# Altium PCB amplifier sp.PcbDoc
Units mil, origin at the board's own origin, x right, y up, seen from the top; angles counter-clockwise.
Board outline 708.66 x 1338.58 mil, 2 copper layers (Top Layer, Bottom Layer); 37 components, 29 nets, 115 pads, 41 vias.
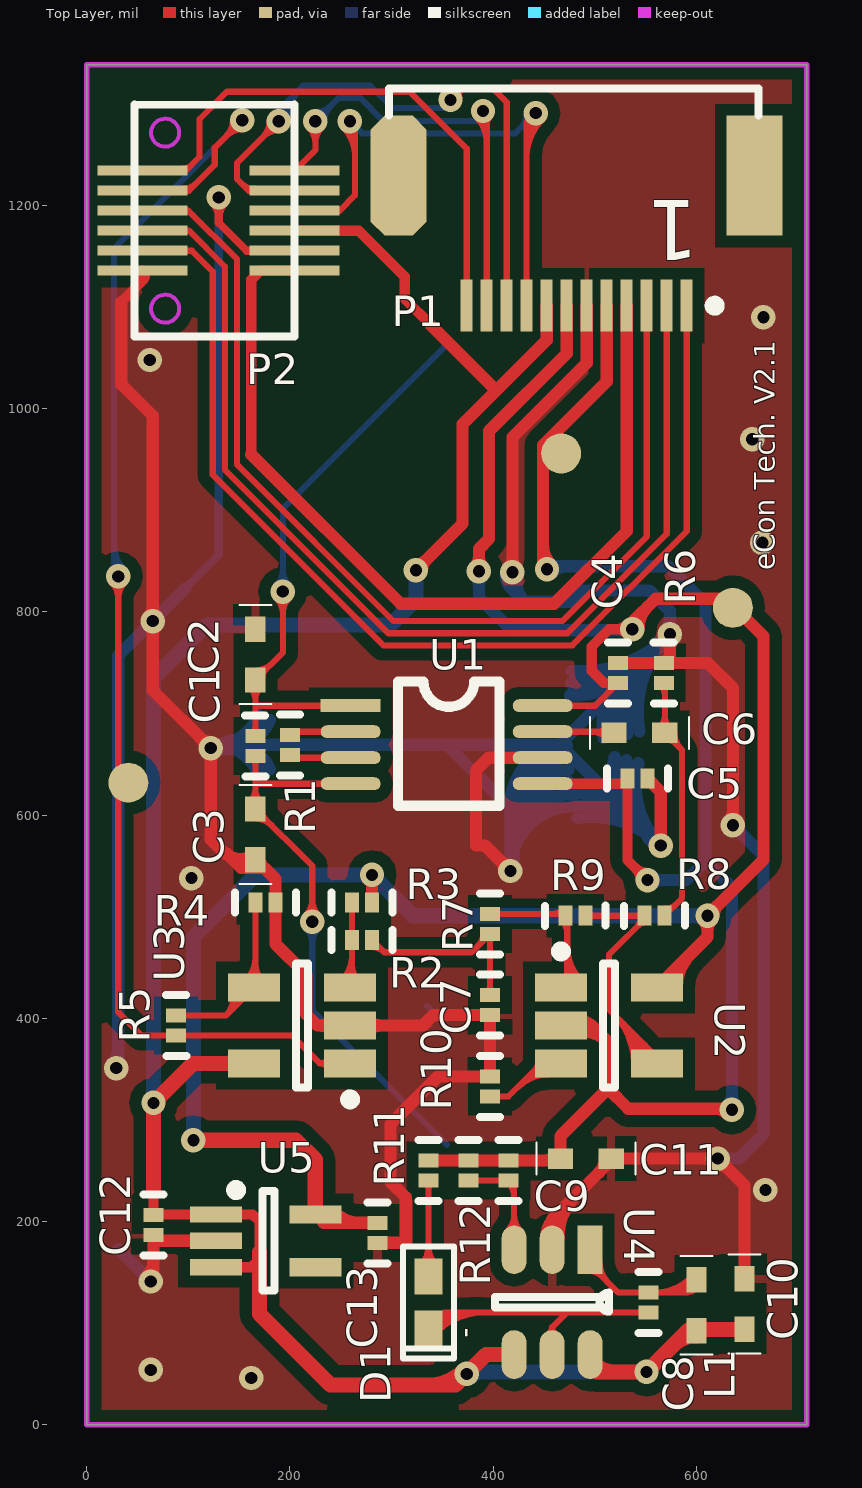
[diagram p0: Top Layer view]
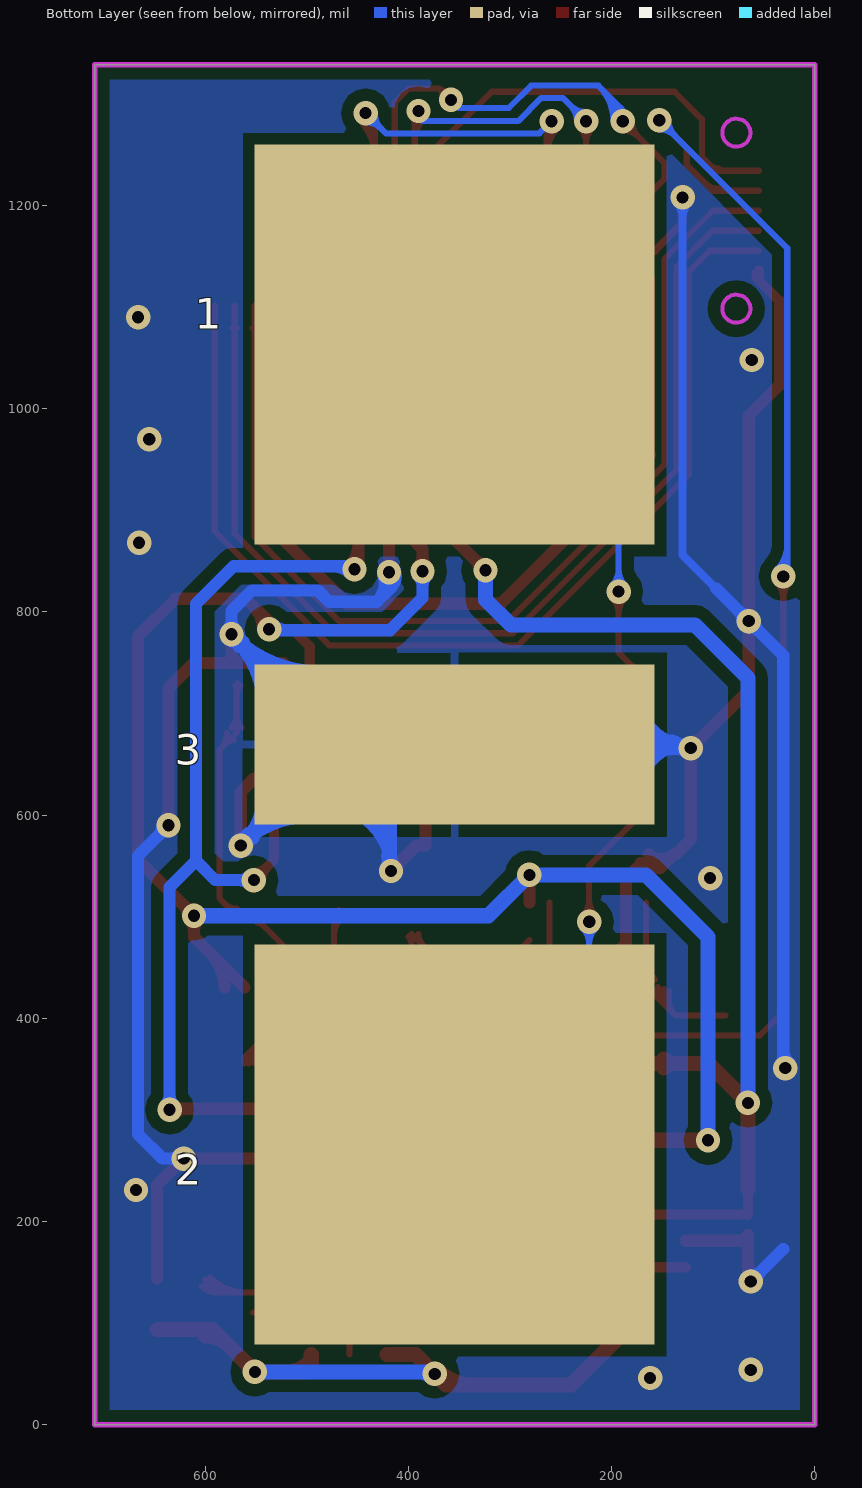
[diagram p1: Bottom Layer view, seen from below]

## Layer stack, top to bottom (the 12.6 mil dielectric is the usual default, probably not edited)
Top Layer: signal copper 1.4
Dielectric: dielectric 12.6, FR-4, Dk 4.8
Bottom Layer: signal copper 1.4

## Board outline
0,0 708.66,0 708.66,1338.58 0,1338.58

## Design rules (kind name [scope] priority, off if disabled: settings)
AssemblyTestPointUsage [All] p1 off:
AssemblyTestpoint [All] p1 off: testpointundercomponent=TRUE minsize=40 maxsize=100 preferedsize=60 minholesize=0 maxholesize=40 preferedholesize=32 testpointgrid=1 usegrid=TRUE gridtolerance=0.01 allowsidetop=TRUE allowsidebottom=TRUE
Clearance Clearance_1 [InPolygon] p1: gap=12
Clearance [All] p2: gap=5
ComponentClearance [All] p1 off: gap=10 collisioncheckmode=3 verticalgap=10 showdistances=FALSE
DiffPairsRouting [All] p1 off: maxlimit=10 minlimit=10 mostfreqgap=10 maxuncoupledlength=500
FabricationTestPointUsage [All] p1 off: valid=0 allowmultiple=FALSE
FabricationTestpoint [All] p1 off: side=3 testpointundercomponent=TRUE minsize=40 maxsize=100 preferedsize=60 minholesize=0 maxholesize=40 preferedholesize=32 testpointgrid=1 allowsidetop=TRUE allowsidebottom=TRUE usegrid=TRUE gridtolerance=0.01
FanoutControl Fanout_BGA [IsBGA] p1 off: bgadir=Out bgaviamode=Centered fanoutstyle=Auto fanoutdirection=Alternating viagrid=1 // Fanout_BGA (Default Rule)
FanoutControl Fanout_LCC [IsLCC] p2 off: bgadir=Out bgaviamode=Centered fanoutstyle=Auto fanoutdirection=Alternating viagrid=1 // Fanout_LCC (Default Rule)
FanoutControl Fanout_SOIC [IsSOIC] p3 off: bgadir=Out bgaviamode=Centered fanoutstyle=Auto fanoutdirection=Alternating viagrid=1 // Fanout_SOIC (Default Rule)
FanoutControl Fanout_Small [(CompPinCount < 5)] p4 off: bgadir=Out bgaviamode=Centered fanoutstyle=Auto fanoutdirection=OutThenIn viagrid=1 // Fanout_Small (Default Rule)
FanoutControl Fanout_Default [All] p5 off: bgadir=Out bgaviamode=Centered fanoutstyle=Auto fanoutdirection=Alternating viagrid=1 // Fanout_Default (Default Rule)
Height [All] p1 off: minheight=0 maxheight=1000 prefheight=500
HoleSize [All] p1 off: absolutevalues=TRUE maxlimit=100 minlimit=1 maxpercent=80.000 minpercent=20.000
HoleToHoleClearance [All] p1 off: gap=10 allowstackedmicrovias=TRUE
LayerPairs [All] p1 off: enforce=TRUE
MinimumSolderMaskSliver [All] p1 off: minsoldermaskwidth=10
NetAntennae [All] p1 off: netantennaetolerance=0
PasteMaskExpansion [All] p1 off: expansion=0
PlaneClearance [All] p1 off: clearance=20
PlaneConnect [All] p1 off: planeconnectstyle=Relief reliefexpansion=20 reliefentries=4 reliefconductorwidth=10 reliefairgap=10
PolygonConnect PolygonConnect_1 [(InPadClass('All Pads'))] p1: connectstyle=Relief reliefconductorwidth=8 reliefentries=4 polygonreliefangle="90 Angle"
PolygonConnect [All] p2: connectstyle=Direct reliefconductorwidth=10 reliefentries=4 polygonreliefangle="90 Angle"
RoomDefinition "amplifier sp" [InComponentClass('amplifier sp')] p1 off: confinementstyle=ConfineIn formatcopy=TRUE lockcomponents=FALSE outline -3149.61,-1968.5 -1149.61,-1968.5 -1149.61,-968.5 -3149.61,-968.5
RoutingCorners [All] p1 off: cornerstyle=45-Degree minsetback=100 maxsetback=100
RoutingLayers [All] p1 off: top layer_v5=TRUE bottom layer_v5=TRUE
RoutingPriority [All] p1 off: routingpriority=0
RoutingTopology [All] p1 off: topology=Shortest
RoutingVias [All] p1: holewidth=12 width=24 viastyle="Through Hole" minholewidth=12 minwidth=24 maxholewidth=12 maxwidth=24
SilkToSilkClearance [All] p1 off: silktosilkclearance=10
SilkscreenOverComponentPads [All] p1 off: minsilkscreentomaskgap=10
SolderMaskExpansion [All] p1 off: expansion=4
Width [All] p1: maxlimit=20 minlimit=6 preferedwidth=6
2 further rules are at their usual default settings.

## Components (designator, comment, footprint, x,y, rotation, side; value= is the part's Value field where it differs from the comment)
1 "Electrode" elec-diff 354.33,1062.99 r270 bottom locked
2 "Electrode" elec-diff 354.33,275.59 r270 bottom locked
3 "Electrode" elec-ref 354.33,669.29 r270 bottom locked
C1 "" 0201 166,668 r90 top
C2 "" "0402 - MI" 166,733 r90 top
C3 "" "0402 - MI" 166,556 r90 top
C4 "Cap" 0201 523,740 r90 top
C5 "Cap" 0201 542,636 r180 top
C6 "" "0402 - MI" 569,681 r180 top
C7 "" 0201 397,413 r90 top
C8 "Cap Semi" 0201 552.91,120.2 r270 top
C9 "Cap Semi" 0201 415.11,250.13 r90 top
C10 "Cap Semi" "0402 - MI" 647.39,143.83 r270 top
C11 "Cap Semi" "0402 - MI" 466.29,261.94 r0 top
C12 "" 0201 65.76,196.75 r90 top
C13 "" 0201 286.24,188.87 r90 top
D1 "" D0402 336.37,120.2 r270 top
L1 "Res3" "0402 - MI" 600.15,92.65 r90 top
P1 "" 12P_0.5mm()FPC 472.44,1165.35 r180 top locked
P2 "Header 2 * 6" btb0.5*12top 125.98,1185.04 r90 top locked
R1 "" 0201 200,669 r270 top
R2 "" 0201 271,477 r180 top
R3 "" 0201 271,514 r180 top
R4 "" 0201 176,514 r0 top
R5 "" 0201 88,393 r90 top
R6 "" 0201 568,740 r270 top
R7 "" 0201 397,493 r270 top
R8 "" 0201 558.84,501 r180 top
R9 "" 0201 480.84,501 r180 top
R10 "" 0201 397,333 r270 top
R11 "" 0201 336.37,250.13 r90 top
R12 "" 0201 375.74,250.13 r270 top
U1 "" MSOP-8 354.33,669.29 r0 top locked
U2 "" SOT23-5AM 514,393 r0 top
U3 "" SOT23-5AM 212,393 r180 top
U4 "" LT3843 454.48,120.2 r270 top
U5 "" SC-70-5 176,181 r0 top

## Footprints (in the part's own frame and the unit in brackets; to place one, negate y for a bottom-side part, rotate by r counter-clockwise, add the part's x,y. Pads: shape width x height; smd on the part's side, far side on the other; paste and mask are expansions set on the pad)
12P_0.5mm()FPC [mm] "Connector; FH12 Series; 13 Position; 0.5mm Spaced Bottom Contact"
  rect 0.3x1.3 smd: 1(-3,1.625) 2(-2.5,1.625) 3(-2,1.625) 4(-1.5,1.625) 5(-1,1.625) 6(-0.5,1.625) 7(0,1.625) 8(0.5,1.625) 9(1,1.625) 10(1.5,1.625) 11(2,1.625) 12(2.5,1.625)
  rect 1.4x3 smd: 13(-4.7,-1.625)
  oct 1.4x3 smd: 14(4.2,-1.625)
  silkscreen extent -4.8,-3.81 4.45,1.75
0201 [mm]
  rect 0.35x0.5 smd: 1(-0.25,0) 2(0.25,0)
  silkscreen extent -0.76,-0.25 0.76,0.25
"0402 - MI" [mil]
  rect 25x20 smd: 1(0,0) 2(50,0)
  silkscreen extent -24,-16 74,16
btb0.5*12top [mm]
  rect 0.25x2.25 smd: 1(-1.25,1.8) 2(-0.75,1.8) 3(-0.25,1.8) 4(0.25,1.8) 5(0.75,1.8) 6(1.25,1.8) 7(1.25,-2) 8(0.75,-2) 9(0.25,-2) 10(-0.25,-2) 11(-0.75,-2) 12(-1.25,-2)
  Keep-Out Layer circle w0.1: c2.2,1.24 r0.35
  Keep-Out Layer circle w0.1: c-2.2,1.24 r0.35
  silkscreen extent -2.9,-2 2.9,2.01
D0402 [mm]
  rect 0.9x0.7 smd: 1(-0.65,0) 2(0.65,0)
  silkscreen extent -1.4,-0.64 1.4,0.64
elec-diff [mm] "12*5mm"
  rect 10x10 smd: 1(0,0)
elec-ref [mm] "12*5mm"
  rect 4x10 smd: 1(0,0)
LT3843 [mm]
  rect 1.22x0.62 smd: 1(-1.321,1.041)
  oval 1.22x0.62 smd: 2(-1.321,0.091) 3(-1.321,-0.859) 4(1.299,-0.859) 5(1.299,0.091) 6(1.299,1.041)
  silkscreen extent -0.25,-1.33 0.23,1.52
MSOP-8 [mm]
  rect 1.5x0.325 smd: 1(-2.4,0.975)
  oval 1.5x0.325 smd: 2(-2.4,0.325) 3(-2.4,-0.325) 4(-2.4,-0.975) 5(2.4,-0.975) 6(2.4,-0.325) 7(2.4,0.325) 8(2.4,0.975)
  silkscreen extent -1.22,-1.52 1.32,1.58
SC-70-5 [mil]
  rect 51.18x16 smd: 1(-49,26) 2(-49,0) 3(-49,-26)
  rect 51.18x18 smd: 4(49,-26) 5(49,26)
  silkscreen extent -34,-49 9,55
SOT23-5AM [mm] "SOT23, 5-Leads, Body 2.9x1.7mm, Pitch 0.95mm, Lead Span 2.8mm, IPC Low Density"
  rect 1.3x0.7 smd: 1(-1.2,0.95) 2(-1.2,0) 3(-1.2,-0.95) 4(1.2,-0.95) 5(1.2,0.95)
  silkscreen extent -1.32,-1.55 0.15,1.97, body extent -0.9,-1.55 0.9,1.55, height 1.45

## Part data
C1 C2 C3 C6 C7 C12 C13: library part Cap, "Capacitor"
C4 C5: "Capacitor"
C8 C9 C10 C11: "Capacitor (Semiconductor SIM Model)"
D1: library part Diode, "Default Diode"
L1: "Resistor"
P1 P2: library part "Header 12", "Header, 12-Pin"
R1 R2 R3 R4 R5 R6 R7 R8 R9 R10 R11 R12: library part Res2, "Resistor"
U1: library part INA128UA, "Precision, Low-Power Instrumentation Amplifiers"
U2 U3: library part AD8603
U4: library part LT3483
U5: library part "RT9013 SOT235"

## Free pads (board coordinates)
  round 39.37 smd: 0(467,956) 1(636,804) 2(41,632)

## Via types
v1: diameter 24, hole 12, Top Layer to Bottom Layer, tented both sides, 37 vias
v2: diameter 24, hole 12, Top Layer to Bottom Layer, 4 vias

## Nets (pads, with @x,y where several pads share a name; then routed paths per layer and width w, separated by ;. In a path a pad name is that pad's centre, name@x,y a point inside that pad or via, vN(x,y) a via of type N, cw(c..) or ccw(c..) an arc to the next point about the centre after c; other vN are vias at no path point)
+3.3V: C10.2 C12.2 L1.1 P1.8 P2.10 U3.5 U4.4 U4.6 U5.1 U5.3 | length 2601.4
  Top Layer w10: 65.76,232.24 C12.2 66.17,207 U5.1 163,207 170,200 170,170 ; U5.3 162,155 170,163 ; P2.10 267.8,1175.2 313,1130 313,1108 339,1082
  Top Layer w12: v1@324,837 v1@326,839 ; v1(324,841) 370,887 370,985 452.76,1067.76 P1.8 ; v1@324,847 ccw(c324,861.49) 334.24,851.24 ccw(c344.49,841) v1@330,841 ; 339,1082 403,1018
  Top Layer w15: 65.76,232.24 v1(65.76,316.76) 104.6,355.6 U3.5 ; U3.5@148.5,351.16 ccw(c137.78,340.44) 137.78,355.6 ccw(c137.78,370.76) U3.5@148.5,360.04 ; 170,170 170,163 170,109 240,39 363,39 v1(374,50) 393.06,69.06 U4.4 ; 336.58,39 ccw(c336.58,87.42) v1@370.82,53.18 ; U4.6 495.48,58.52 502,52 v1(551,52) 592.83,93.83 C10.2 ; U4.6@498.81,60.57 ccw(c519.5,81.26) 519.5,52 ; 577.1,78.1 cw(c600.15,55.04) L1.1@600.15,87.65
  Bottom Layer w15: v1(65.76,316.76) 65.76,734.76 118,787 299,787 324,812 v1(324,841) ; v1(374,50) 373,50 375,52 v1(551,52) ; v1@377.18,46.82 cw(c389.69,34.31) 389.69,52
+3.7V: P1.4 P2.12 | length 900.3
  Top Layer w10: 162,955 162,1127 170.83,1135.83 P2.12
  Top Layer w12: 162,955 309,808 460,808 531.5,879.5 P1.4
+VS: C4.1 C13.2 P1.7 pad.1 R3.1 U1.8 U2.5 U5.5 | length 2503.4
  Top Layer w6: U1.8 500.52,707.68 C4.1 ; U1.8@474.35,705.27 cw(c480.15,699.47) 480.15,707.68 cw(c480.15,715.88) U1.8@474.35,710.08 ; 511.32,718.48 ccw(c499.64,730.16) C4.1@516.16,730.16
  Top Layer w10: C4.1 508.84,730.16 497,742 497,766 514,783 v1(537,783) ; v1@532.05,778.05 ccw(c520.1,766.1) 520.1,783 ccw(c520.1,799.9) v1@532.05,787.95
  Top Layer w12: U5.5 233.28,198.72 C13.2 ; U5.5@243.71,209.12 ccw(c268.83,234.24) 268.83,198.72 ; R3.1 v2(280.84,541.16) v2@280.84,541.84 ; v1@381.76,844.24 ccw(c371.51,854.49) 386,854.49 ccw(c400.49,854.49) v1@390.24,844.24 ; v1(386,840) 386,862 396,872 396,978 472.44,1054.44 P1.7 ; v1(537,783) 537,790 560,813 629,813 666,776 666,556 v1(611,501) 611,480.16 U2.5 ; v1@543,783 cw(c574.38,783) 552.19,805.19 ; U2.5@580.83,430.4 cw(c628.13,430.4) 594.69,463.84 ; v1@606.76,496.76 cw(c596.51,486.51) 611,486.51 cw(c625.49,486.51) v1@615.24,496.76 ; v1@611,507 ccw(c611,521.49) 621.24,511.24 ccw(c631.49,501) v1@617,501
  Top Layer w15: v1(105,280) 206,280 225,261 U5.5
  Bottom Layer w12: v2(280.84,541.16) v2@281,541 ; v1@381.76,835.76 cw(c371.51,825.51) 386,825.51 cw(c400.49,825.51) v1@390.24,835.76 ; v1(386,840) 386,814 418,782 537,782 538,783 v1(537,783) ; 520.1,782 ccw(c520.1,799.9) v1@532.76,787.24 ; 524.93,782 cw(c524.93,770.93) v1@532.76,778.76
  Bottom Layer w15: v1(105,280) 105,480 166,541 281,541 321,501 v1(611,501)
-VS: C5.2 C9.2 C11.1 P1.5 pad.0 R11.2 R12.1 U1.5 U2.2 | length 1923.2
  Top Layer w10: U1.5 C5.2@527.06,630.91 ; 522.42,630.91 ccw(c522.42,642.78) C5.2@530.82,634.38 ; C5.2 532.16,555.84 v1(552,536) ; v1@545,536 ccw(c528.1,536) 540.05,547.95 ccw(c552,559.9) v1@552,543
  Top Layer w12: R11.2 R12.1 C9.2 464.32,259.97 C11.1 466.29,284.29 513,331 ; 449,866.14 ccw(c477.14,866.14) v1@457.24,846.24 ; 449.38,259.97 ccw(c449.38,276.35) C11.1@460.96,264.77 ; v1(453,842) 450,842 449,841 449,964 511.81,1026.81 P1.5 ; U2.2 497,393 ; U2.2@477.44,397.07 cw(c483.21,376.29) 498.46,391.54 ; U2.2@480.65,385.5 cw(c489.54,353.54) 513,377 ; U2.2@484.14,387.57 cw(c497,375.05) 497,393 ; U2.2@484.14,398.43 ccw(c497,410.95) 497,393 ; 618.1,311 cw(c618.1,293.1) v1@630.76,305.76 ; 622.93,311 ccw(c622.93,322.07) v1@630.76,314.24 ; v1(635,310) 634,311 533,311 513,331 ; 497,393 513,377 ; 513,331 513,377
  Bottom Layer w12: v1(453,842) 450,842 453,845 572,845 609,808 609,555 ; v1@457.24,837.76 cw(c474.73,820.27) 474.73,845 ; v1(552,536) 590,536 609,555 ; v1@556.24,531.76 cw(c566.49,521.51) 566.49,536 cw(c566.49,550.49) v1@556.24,540.24 ; v1@630.76,314.24 ccw(c620.51,324.49) 635,324.49 ccw(c649.49,324.49) v1@639.24,314.24 ; v1(635,310) 635,529 609,555
GND: 3.1 C2.2 C3.1 C4.2 C5.1 C7.1 C10.1 C11.2 C12.1 C13.1 P1.6 P2.1 P2.11 R4.2 R6.1 R10.1 U1.6 U3.2 U4.2 U5.2 | length 7892.9
  Top Layer w8: v2@124.34,1202.34 cw(c110.69,1188.69) 130,1188.69 cw(c149.31,1188.69) v2@135.66,1202.34 ; v2(130,1208) 130,1183 157.49,1155.51 P2.11
  Top Layer w10: 34,1105 55.12,1126.12 ; P2.1 55.12,1126.12 ; P2.1@55.17,1135.88 cw(c50.21,1131.03) 55.12,1126.12
  Top Layer w12: 34,1105 34,1024 65,993 v1(65,791) 65,723 v1(122,666) 122,576 136,562 138,562 ; v1@58.76,145.24 ccw(c41.84,162.16) 65.76,162.16 ; v1@60.76,786.76 cw(c50.51,776.51) 65,776.51 cw(c79.49,776.51) v1@69.24,786.76 ; v1@60.76,795.24 ccw(c50.51,805.49) 65,805.49 ccw(c79.49,805.49) v1@69.24,795.24 ; v1(63,141) 65.76,143.76 C12.1 71.67,181 U5.2 ; v1@116,666 ccw(c101.51,666) 111.76,676.24 ccw(c122,686.49) v1@122,672 ; v1@117.76,661.76 cw(c107.51,651.51) 122,651.51 cw(c136.49,651.51) v1@126.24,661.76 ; 146.86,553.14 ccw(c159.41,565.69) C3.1@171.41,552.6 ; C3.1@162.28,554.98 cw(c152,559.07) 152,548 ; C3.1@163.3,561.45 cw(c150.94,574.94) 138,562 ; C3.1@166,549.5 cw(c166,531.39) 178.8,544.2 ; U3.2@241.93,387.5 ccw(c228.65,374.22) 228.65,393 ccw(c228.65,411.78) U3.2@241.93,398.5 ; U3.2@276.56,387.5 cw(c289.84,374.22) 289.84,393 cw(c289.84,411.78) U3.2@276.56,398.5 ; C13.1 311.03,179.03 314,182 314,224 299,239 299,296 345.84,342.84 R10.1 C7.1 341.16,403.16 331,393 U3.2 227,393 216,404 216,443 185.84,473.16 R4.2 185.84,537.16 175,548 152,548 ; v1@411,545 ccw(c396.51,545) 406.76,555.24 ccw(c417,565.49) v1@417,551 ; v1@414.76,843.24 ccw(c404.51,853.49) 419,853.49 ccw(c433.49,853.49) v1@423.24,843.24 ; v1(417,545) 392,570 383,570 383,644 395.5,656.5 U1.6 ; v1(419,839) 419,972 492.13,1045.13 P1.6 ; U4.2@452.28,184.02 cw(c481.9,184.02) 460.96,204.96 ; U4.2@453.69,188.4 ccw(c443.1,199) 458.08,199 ccw(c473.06,199) U4.2@462.47,188.4 ; U4.2 458.08,202.08 516.29,260.29 C11.2 v1(621.06,261.94) 647.39,235.61 C10.1 ; U4.2@464.28,184.02 cw(c522.87,184.02) 481.44,225.44 ; 504.03,248.03 ccw(c490.13,261.94) C11.2@509.79,261.94 ; C4.2 R6.1 ; C5.1 565,622.84 v1(565,570) ; v1@569.76,773.76 cw(c559.51,763.51) 574,763.51 cw(c588.49,763.51) v1@578.24,773.76 ; v1(574,778) 574,755.84 R6.1 ; v1@616.82,257.69 ccw(c606.58,247.45) 606.58,261.94 ccw(c606.58,276.42) v1@616.82,266.18 ; v1@621.06,255.94 cw(c621.06,241.45) 631.31,251.69 cw(c641.55,261.94) v1@627.06,261.94 ; v1@631.76,594.24 ccw(c621.51,604.49) 636,604.49 ccw(c650.49,604.49) v1@640.24,594.24 ; v1(636,590) 636,725 611.16,749.84 R6.1 ; 138,562 152,548
  Bottom Layer w8: 97,823 130,856 v2(130,1208) ; v2@124.34,1202.34 cw(c110.69,1188.69) 130,1188.69 cw(c149.31,1188.69) v2@135.66,1202.34
  Bottom Layer w12: v1@24.76,355.24 ccw(c9.69,370.31) 31,370.31 ; 31,173 v1(63,141) ; v1@31,351 31,757 v1(65,791) 97,823 ; v1@57,141 ccw(c42.51,141) 52.76,151.24 ccw(c63,161.49) v1@63,147 ; v1@59,791 cw(c44.51,791) 54.76,780.76 cw(c65,770.51) v1@65,785 ; v1@65,797 ccw(c65,811.49) 75.24,801.24 ccw(c85.49,791) v1@71,791 ; v1(122,666) v1@125.29,669.29 ; v1@125.66,661.25 cw(c137.59,645.75) 142.65,664.64 ; v1@126.24,661.76 cw(c144.43,643.57) 144.43,669.29 ; v1@127.2,663 cw(c146.62,651.79) 140.81,673.45 ; 3.1@169.51,640.3 ccw(c125.29,621.08) v1@125.29,669.29 ; 3.1@169.51,698.28 cw(c125.29,717.5) v1@125.29,669.29 ; 3.1@180.51,645.08 ccw(c143.59,629.04) 143.59,669.29 ccw(c143.59,709.55) 3.1@180.51,693.5 ; v1@412.76,549.24 ccw(c402.51,559.49) 417,559.49 ccw(c431.49,559.49) v1@421.24,549.24 ; v1@413.32,840.93 ccw(c429.23,835.53) 417.35,823.65 ; v1@414,550.2 ccw(c407.17,562.02) 420.36,558.49 ; v1@414.76,834.76 cw(c404.51,824.51) 419,824.51 cw(c433.49,824.51) v1@423.24,834.76 ; v1(417,545) 417,606.62 3.1 ; v1@417,545.94 cw(c479.83,545.94) 3.1@476.07,608.66 ; 417,558.68 cw(c479.07,558.68) 3.1@475.36,620.64 ; 417,571.42 cw(c478.31,571.42) 3.1@474.64,632.62 ; 417,584.16 cw(c477.54,584.16) 3.1@473.92,644.6 ; 3.1@417,596.9 cw(c476.78,596.9) 3.1@473.2,656.57 ; 3.1@417,609.64 cw(c476.02,609.64) 3.1@472.49,668.55 ; v1(419,839) 419,822 431,810 ; 420.67,559.62 ccw(c435.46,555.66) v1@422.2,548 ; v1@424.68,837.07 ccw(c449.62,828.62) 431,810 ; 3.1@475.8,717.92 ccw(c481.22,796.22) 3.1@536.72,740.72 ; 3.1@476.63,729.89 ccw(c483.63,831.09) 555.36,759.36 ; 3.1@477.46,741.86 ccw(c486.04,865.95) v1(574,778) ; 3.1@479.42,621.05 cw(c488.13,560.87) 3.1@531.13,603.87 ; 3.1@481.14,609.18 cw(c492.41,531.29) 548.06,586.94 ; 3.1@482.86,597.3 cw(c496.69,501.7) v1(565,570) ; 3.1@508.6,675.82 cw(c568.12,686.58) 3.1@525.35,729.35 ; 3.1@519.63,657.1 ccw(c577.69,642.11) 3.1@535.29,599.71 ; 3.1@520.4,677.96 cw(c595.59,691.54) 3.1@541.56,745.56 ; 3.1@531.25,654.1 ccw(c601.3,636.01) 550.14,584.86 ; 3.1@532.21,680.09 cw(c623.06,696.5) 557.78,761.78 ; 3.1@542.87,651.1 ccw(c624.91,629.92) v1(565,570) ; 3.1@544.02,682.22 cw(c650.52,701.47) v1(574,778) ; v1@559,570 ccw(c544.51,570) 554.76,580.24 ccw(c565,590.49) v1@565,576 ; v1@559.2,568.45 ccw(c545.21,564.7) 552.45,577.25 ccw(c559.7,589.78) v1@563.45,575.8 ; v1@559.2,571.55 ccw(c545.22,575.3) 557.76,582.54 ccw(c570.3,589.79) v1@566.55,575.8 ; 561.84,770.12 ccw(c553.96,782.28) v1@568.13,779.25 ; 561.85,770.12 cw(c569.72,757.97) v1@572.75,772.13 ; v1@568,778 cw(c553.51,778) 563.76,767.76 cw(c574,757.51) v1@574,772 ; v1@568.17,776.56 cw(c554.12,773.09) 566.51,765.61 cw(c578.91,758.11) v1@575.44,772.17 ; v1@569.76,782.24 ccw(c559.51,792.49) 574,792.49 ccw(c588.49,792.49) v1@578.24,782.24 ; v1(621.06,261.94) 641.94,261.94 666,286 666,560 v1(636,590) ; v1@625.31,257.69 cw(c635.55,247.45) 635.55,261.94 cw(c635.55,276.42) v1@625.31,266.18 ; v1@636,584 cw(c636,569.51) 646.24,579.76 cw(c656.49,590) v1@642,590 ; v1@125.29,669.29 3.1 ; 3.1 3.1@465.71,669.29 ; 431,810 478,810 489,821 554,821 574,801 v1(574,778) ; 3.1@465.71,669.29 v1(565,570) ; 3.1@465.71,669.29 465.71,669.71 v1(574,778)
  other v1: 162,46 63,54 668,231 29,351 103,538 665,868 655,970 62,1048 666,1090
Net1_1: 1.1 C1.2 C2.1 U1.1 | length 706
  Top Layer w6: C2.1@161.05,725.55 cw(c149.1,713.6) 166,713.6 cw(c182.9,713.6) C2.1@170.95,725.55 ; C1.2@163.25,680.59 ccw(c156.61,687.23) 166,687.23 ccw(c175.39,687.23) C1.2@168.75,680.59 ; C1.2 166,707.68 ; C2.1@166,742.5 ccw(c166,765.44) 182.22,749.22 ; C2.1@173,735.5 cw(c183.86,735.5) 176.18,743.18 ; v2@186.64,813.64 cw(c171.27,798.27) 193,798.27 cw(c214.73,798.27) v2@199.36,813.64 ; v2(193,820) 193,760 C2.1 166,707.68 ; U1.1@234.31,705.27 ccw(c228.51,699.47) 228.51,707.68 ccw(c228.51,715.88) U1.1@234.31,710.08 ; U1.1 166,707.68
  Bottom Layer w6: v2@186.64,826.36 ccw(c171.27,841.73) 193,841.73 ccw(c214.73,841.73) v2@199.36,826.36 ; v2(193,820) 193,901.66 1.1
Net2_1: 2.1 C1.1 C3.2 U1.4 | length 737.8
  Top Layer w6: C3.2@161.05,613.45 ccw(c149.1,625.4) 166,625.4 ccw(c182.9,625.4) C3.2@170.95,613.45 ; C1.1@163.25,655.41 cw(c156.61,648.77) 166,648.77 cw(c175.39,648.77) C1.1@168.75,655.41 ; C3.2@166,596.5 cw(c166,573.57) 182.22,589.78 ; C1.1 166,632.08 ; C3.2@173,603.5 ccw(c183.86,603.5) 176.18,595.82 ; v2@215.64,501.36 ccw(c200.27,516.73) 222,516.73 ccw(c243.73,516.73) v2@228.36,501.36 ; v2(222,495) 222,550 C3.2 166,632.08 ; U1.4@234.31,628.5 ccw(c228.51,622.7) 228.51,630.91 ccw(c228.51,639.11) U1.4@234.31,633.31 ; U1.4 167.17,630.91 166,632.08
  Bottom Layer w6: v2@215.64,488.64 cw(c200.27,473.27) 222,473.27 cw(c243.73,473.27) v2@228.36,488.64 ; 2.1@217.26,412.66 ccw(c205.81,424.11) 2.1@222,424.11 ; v2(222,495) 222,407.92 2.1 ; 2.1@335,412 2.1@350,397
NetC6_1: C6.1 R6.2 R8.1 | length 324.6
  Top Layer w6: C6.1@564.05,685.95 ccw(c552.1,697.9) 569,697.9 ccw(c585.9,697.9) C6.1@573.95,685.95 ; R6.2@565.25,727.41 cw(c556.2,718.35) 569,718.35 ; R6.2 569,729.16 C6.1 586,664 586,518.32 R8.1 ; R8.1@568.68,507.84 ccw(c568.68,524.36) 580.37,512.68 ; 569,723.18 cw(c574.98,723.18) R6.2@570.75,727.41 ; C6.1@571.5,674 cw(c571.5,663.14) 579.18,670.82 ; C6.1@578.5,681 ccw(c601.43,681) 585.22,664.78
NetC6_2: C6.2 U1.7 | length 110.1
  Top Layer w6: U1.7 517.91,682.09 C6.2 ; U1.7@474.35,679.68 cw(c480.15,673.88) 480.15,682.09 cw(c480.15,690.29) U1.7@474.35,684.49 ; 496.98,682.09 cw(c496.98,661.48) C6.2@511.55,676.05 ; 502.22,682.09 ccw(c502.22,695.28) C6.2@511.55,685.95
NetC7_2: C7.2 R2.1 R7.2 | length 244.4
  Top Layer w6: R2.1@280.84,470.16 cw(c280.84,453.64) 292.52,465.32 ; R2.1 292.84,465 378.84,465 R7.2 C7.2 ; 385.32,471.48 ccw(c373.64,483.16) R7.2@390.16,483.16 ; C7.2@394.25,425.59 ccw(c387.61,432.23) 397,432.23 ccw(c406.39,432.23) C7.2@399.75,425.59 ; R7.2@394.25,480.41 cw(c387.61,473.77) 397,473.77 cw(c406.39,473.77) R7.2@399.75,480.41
NetC8_1: C8.1 L1.2 U4.1 | length 289.9
  Top Layer w6: U4.1@495.48,151.19 cw(c495.48,135.91) 506.29,146.71 ; U4.1 495.48,157.52 522.95,130.05 C8.1 587.55,130.05 ; U4.1@498.69,160.39 ccw(c513.36,160.39) U4.1@502.98,150.02 ; U4.1@504.68,160.39 ccw(c533.85,160.39) 513.23,139.77 ; C8.1@558.87,130.05 ccw(c558.87,181.43) L1.2@595.2,145.1 ; 573.36,130.05 ccw(c573.36,166.94) L1.2@599.44,140.85 ; 587.84,130.05 ccw(c587.84,152.45) L1.2@603.69,136.61 ; 589.97,132.46 ccw(c582.29,140.15) L1.2@593.15,140.15 ; L1.2@598.66,133.31 ccw(c596.09,121.51) 587.55,130.05 ; L1.2 587.55,130.05
NetC8_2: C8.2 D1.2 U4.5 | length 435
  Top Layer w6: D1.2@335.51,99.41 cw(c361.94,72.98) 361.94,110.36 ; D1.2 352.12,110.36 ; D1.2@339.75,95.17 cw(c376.42,58.5) 376.42,110.36 ; D1.2@340.87,108.35 ccw(c345.05,117.43) 352.12,110.36 ; D1.2@343.99,90.93 cw(c390.91,44.01) 390.91,110.36 ; D1.2@347.15,98.55 cw(c363.67,98.55) 351.99,110.23 ; U4.5@453.81,89.02 ccw(c450.11,96.08) 458.08,96.08 ; U4.5 458.08,96.08 ; U4.5@462.35,89.02 cw(c466.05,96.08) 458.08,96.08 ; C8.2 472.36,110.36 ; 352.12,110.36 472.36,110.36 ; 458.08,96.08 472.36,110.36
NetC9_1: C9.1 R12.2 U4.3 | length 159
  Top Layer w6: R12.2 C9.1 420.68,234.72 U4.3 ; U4.3@414.17,190.52 ccw(c398.45,206.24) 420.68,206.24 ccw(c442.9,206.24) U4.3@427.19,190.52 ; C9.1@415.31,237.53 cw(c402.36,224.58) 420.68,224.58
NetD1_1: D1.1 R11.1 | length 150.1
  Top Layer w6: D1.1@328.75,157.35 ccw(c310.35,175.76) 336.37,175.76 ccw(c362.39,175.76) D1.1@343.99,157.35 ; R11.1@333.62,237.53 cw(c326.98,230.89) 336.37,230.89 cw(c345.76,230.89) R11.1@339.12,237.53 ; D1.1 R11.1
NetR1_1: R1.1 U1.2 | length 74.1
  Top Layer w6: R1.1 203.24,682.09 U1.2 ; U1.2@234.31,679.68 ccw(c228.51,673.88) 228.51,682.09 ccw(c228.51,690.29) U1.2@234.31,684.49
NetR1_2: R1.2 U1.3 | length 73.8
  Top Layer w6: R1.2 202.66,656.5 U1.3 ; U1.3@234.31,654.09 ccw(c228.51,648.29) 228.51,656.5 ccw(c228.51,664.7) U1.3@234.31,658.9
NetR2_2: R2.2 R3.2 U3.3 | length 139.5
  Top Layer w6: U3.3@251.62,438.02 ccw(c228.6,461.04) 261.16,461.04 ; U3.3@255.86,433.78 ccw(c243.09,446.56) 261.16,446.56 ; U3.3 261.16,432.31 R2.2 R3.2 ; 261.16,451.81 ccw(c280.65,451.81) U3.3@266.87,438.02
NetR4_1: R4.1 R5.2 U3.4 | length 288.4
  Top Layer w6: R5.2 137.2,402.84 ; U3.4@142.75,426.89 cw(c120.73,419.31) 137.2,402.84 ; 143.99,409.63 ccw(c130.83,422.79) U3.4@148.43,428.85 ; 150.78,416.42 ccw(c140.94,426.27) U3.4@154.1,430.8 ; U3.4@157.13,438.02 ccw(c135.35,459.81) 166.16,459.81 ; U3.4@161.38,433.78 ccw(c149.83,445.32) 166.16,445.32 ; 166.16,453.04 ccw(c187.4,453.04) U3.4@172.38,438.02 ; R4.1 166.16,431.8 U3.4 137.2,402.84
NetR7_1: R7.1 R9.2 U2.1 | length 231.2
  Top Layer w6: R7.1 469.16,502.84 R9.2 473,499 473,436.65 U2.1 ; 458.93,502.84 ccw(c458.93,516.02) R9.2@468.25,506.7 ; R9.2@468.25,495.3 cw(c456.78,483.83) 473,483.83 ; 473,455.38 ccw(c503.55,455.38) U2.1@481.95,433.78 ; 473,469.87 ccw(c518.03,469.87) U2.1@486.19,438.02
NetR8_2: R8.2 R9.1 U2.4 | length 433.9
  Top Layer w6: R9.1 R8.2 549.71,501 551,499.71 514,462.71 514,409 561.24,361.76 U2.4 ; R9.1@493.44,498.25 cw(c500.08,491.61) 500.08,501 cw(c500.08,510.39) R9.1@493.44,503.75 ; 518.33,404.67 cw(c469.25,355.6) U2.4@538.65,355.6 ; 528.57,394.43 cw(c489.73,355.6) U2.4@544.65,355.6 ; 538.81,384.19 cw(c510.22,355.6) U2.4@550.65,355.6 ; 542.12,490.83 ccw(c534.9,498.05) R8.2@545.11,498.05 ; R8.2@542.94,491.65 cw(c549,485.58) R8.2@549,494.16 ; R8.2@546.25,498.25 ccw(c539.61,491.61) 539.61,501 ccw(c539.61,510.39) R8.2@546.25,503.75 ; 549.05,373.95 cw(c530.71,355.6) U2.4@556.65,355.6
NetR10_2: R10.2 U2.3 | length 147.1
  Top Layer w6: R10.2 415.16,323.16 447.6,355.6 U2.3 ; 424,332 cw(c454.94,301.06) U2.3@454.94,344.82 ; 434.24,342.24 cw(c454.94,321.54) U2.3@454.94,350.82 ; U2.3@441.74,349.74 ccw(c435.88,355.6) U2.3@444.17,355.6
V1: P1.9 P2.9 | length 725.5
  Top Layer w6: P2.9 248.88,1194.88 264,1210 264,1278 v1(259,1283) ; v1@252.64,1276.64 cw(c225.2,1249.2) 264,1249.2 ; v1@256.88,1280.88 cw(c239.69,1263.69) 264,1263.69 ; P1.9@431.02,1123.12 ccw(c426.23,1127.91) 433,1127.91 ; 433,1128.25 ccw(c440.26,1128.25) P1.9@435.13,1123.12 ; 433,1247.54 cw(c485.46,1247.54) v1@448.36,1284.64 ; 433,1262.03 cw(c470.97,1262.03) v1@444.12,1288.88 ; 433,1276.51 cw(c456.49,1276.51) v1@439.88,1293.12 ; P1.9 433,1101.45 433,1282 ; v1@433.88,1287.12 cw(c429.82,1285.18) 433,1282 ; v1@438.12,1282.88 ccw(c436.18,1278.82) 433,1282 ; v1(442,1291) 433,1282
  Bottom Layer w6: v1(259,1283) 271,1271 422,1271 v1(442,1291) ; v1@433,1291 cw(c411.27,1291) 426.64,1275.64 cw(c442,1260.27) v1@442,1282
V2: P1.10 P2.8 | length 763.6
  Top Layer w6: 151.97,1222.03 ccw(c165.35,1235.42) P2.8@165.35,1216.49 ; v1@180,1283 cw(c158.27,1283) 173.64,1267.64 cw(c189,1252.27) v1@189,1274 ; v1(189,1283) 148,1242 148,1226 159.43,1214.57 P2.8 ; v1(358,1304) 369.35,1315.35 ; v1@360.11,1312.75 ccw(c362.41,1322.3) 369.35,1315.35 ; v1@366.75,1306.11 cw(c376.3,1308.41) 369.35,1315.35 ; P1.10@411.33,1123.12 ccw(c406.37,1128.08) 413.39,1128.08 ccw(c420.4,1128.08) P1.10@415.44,1123.12 ; P1.10 413.39,1301.61 399.65,1315.35 369.35,1315.35
  Bottom Layer w6: v1@186,1283 cw(c205.31,1283) 191.66,1296.66 ; v1(189,1283) 189,1294 213,1318 279,1318 301,1296 350,1296 v1(358,1304) ; v1@192,1283 cw(c225.8,1283) 201.9,1306.9 ; v1@198,1283 cw(c246.28,1283) 212.14,1317.14
V3: P1.11 P2.7 | length 571.3
  Top Layer w6: P2.7 225,1254.53 v1(225,1283) ; v1@218.64,1276.64 cw(c203.27,1261.27) 225,1261.27 cw(c246.73,1261.27) v1@231.36,1276.64 ; v1@383.64,1286.64 cw(c359.34,1262.34) 393.7,1262.34 ; v1@387.88,1290.88 cw(c373.82,1276.82) 393.7,1276.82 ; P1.11@391.65,1123.12 ccw(c386.69,1128.08) 393.7,1128.08 ccw(c400.72,1128.08) P1.11@395.76,1123.12 ; P1.11 v1@393.7,1286.3 ; 393.7,1280.21 cw(c402.79,1280.21) v1@396.36,1286.64
  Bottom Layer w6: v1(225,1283) 248,1306 269,1306 292,1283 386,1283 396,1293 v1(390,1293) ; v1@225,1292 ccw(c225,1313.73) 240.36,1298.36 ccw(c255.73,1283) v1@234,1283
V4: P1.12 P2.6 | length 570.5
  Top Layer w6: P2.6 97.25,1234.25 111,1248 111,1285 138,1312 318,1312 374.02,1255.98 P1.12 ; P2.6@94.49,1236.17 ccw(c94.49,1247.48) 102.49,1239.49 ; P1.12@371.96,1123.12 ccw(c367,1128.08) 374.02,1128.08 ccw(c381.03,1128.08) P1.12@376.07,1123.12
V5: P2.5 pad.2 R5.1 U3.1 | length 1506.6
  Top Layer w6: v1@24.64,828.64 cw(c9.27,813.27) 31,813.27 cw(c52.73,813.27) v1@37.36,828.64 ; v1(31,835) 31,406 53.84,383.16 R5.1 201.84,383.16 229.4,355.6 ; P2.5 100.57,1214.57 126,1240 126,1257 v1(153,1284) ; P2.5@94.49,1216.49 ccw(c94.49,1235.8) 108.15,1222.14 ; v1@144,1284 cw(c122.27,1284) 137.64,1268.64 cw(c153,1253.27) v1@153,1275 ; U3.1@237.94,350.5 ccw(c229.4,345.91) 229.4,355.6 ; U3.1@237.94,360.7 cw(c229.4,365.29) 229.4,355.6 ; U3.1 229.4,355.6
  Bottom Layer w6: v1@24.64,841.36 ccw(c18.93,847.07) 27,847.07 ; 27,851.9 ccw(c47.9,851.9) v1@33.12,837.12 ; 27,866.38 ccw(c62.38,866.38) v1@37.36,841.36 ; v1(31,835) 27,839 27,1158 v1(153,1284) ; v1@144,1284 cw(c122.27,1284) 137.64,1268.64 cw(c153,1253.27) v1@153,1275
V6: P1.3 P2.4 | length 1054.4
  Top Layer w6: P2.4 100.12,1194.88 148,1147 148,944.96 301.96,791 468.03,791 551.18,874.15 P1.3 ; P1.3@549.13,1079.64 cw(c544.17,1074.68) 551.18,1074.68 cw(c558.2,1074.68) P1.3@553.24,1079.64
V7: P1.2 P2.3 | length 1073.1
  Top Layer w6: P2.3 100.8,1175.2 136,1140 136,939.99 296.99,779 473,779 570.87,876.87 P1.2 ; P1.2@568.81,1079.64 cw(c563.85,1074.68) 570.87,1074.68 cw(c577.88,1074.68) P1.2@572.92,1079.64
V8: P1.1 P2.2 | length 1093
  Top Layer w6: P2.2 103.49,1155.51 124,1135 124,935.02 292.02,767 477.97,767 590.55,879.58 P1.1 ; P1.1@588.5,1079.64 cw(c583.54,1074.68) 590.55,1074.68 cw(c597.57,1074.68) P1.1@592.61,1079.64
pads on no net: P1.13 P1.14 U5.4

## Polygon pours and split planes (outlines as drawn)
GND on Top Layer "G" (solid, remove dead copper, pour order 4): 0,1338.58 708.66,1338.58 708.66,0 0,0
GND on Bottom Layer "G" (solid, remove dead copper, pour order 3): 0,1338.58 708.66,1338.58 708.66,0 0,0

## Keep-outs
Keep-Out Layer:
  the board outline again, w5

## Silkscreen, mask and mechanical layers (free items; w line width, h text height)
Top Overlay:
  text "eCon Tech. V2.1" at 677,841 h20 r90
Mechanical 1:
  the board outline again, w10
